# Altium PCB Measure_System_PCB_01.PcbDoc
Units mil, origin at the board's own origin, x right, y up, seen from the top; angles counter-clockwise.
Board outline 2560.03 x 2760.03 mil, 2 copper layers (Top Layer, Bottom Layer); 42 components, 34 nets, 113 pads, 0 vias.
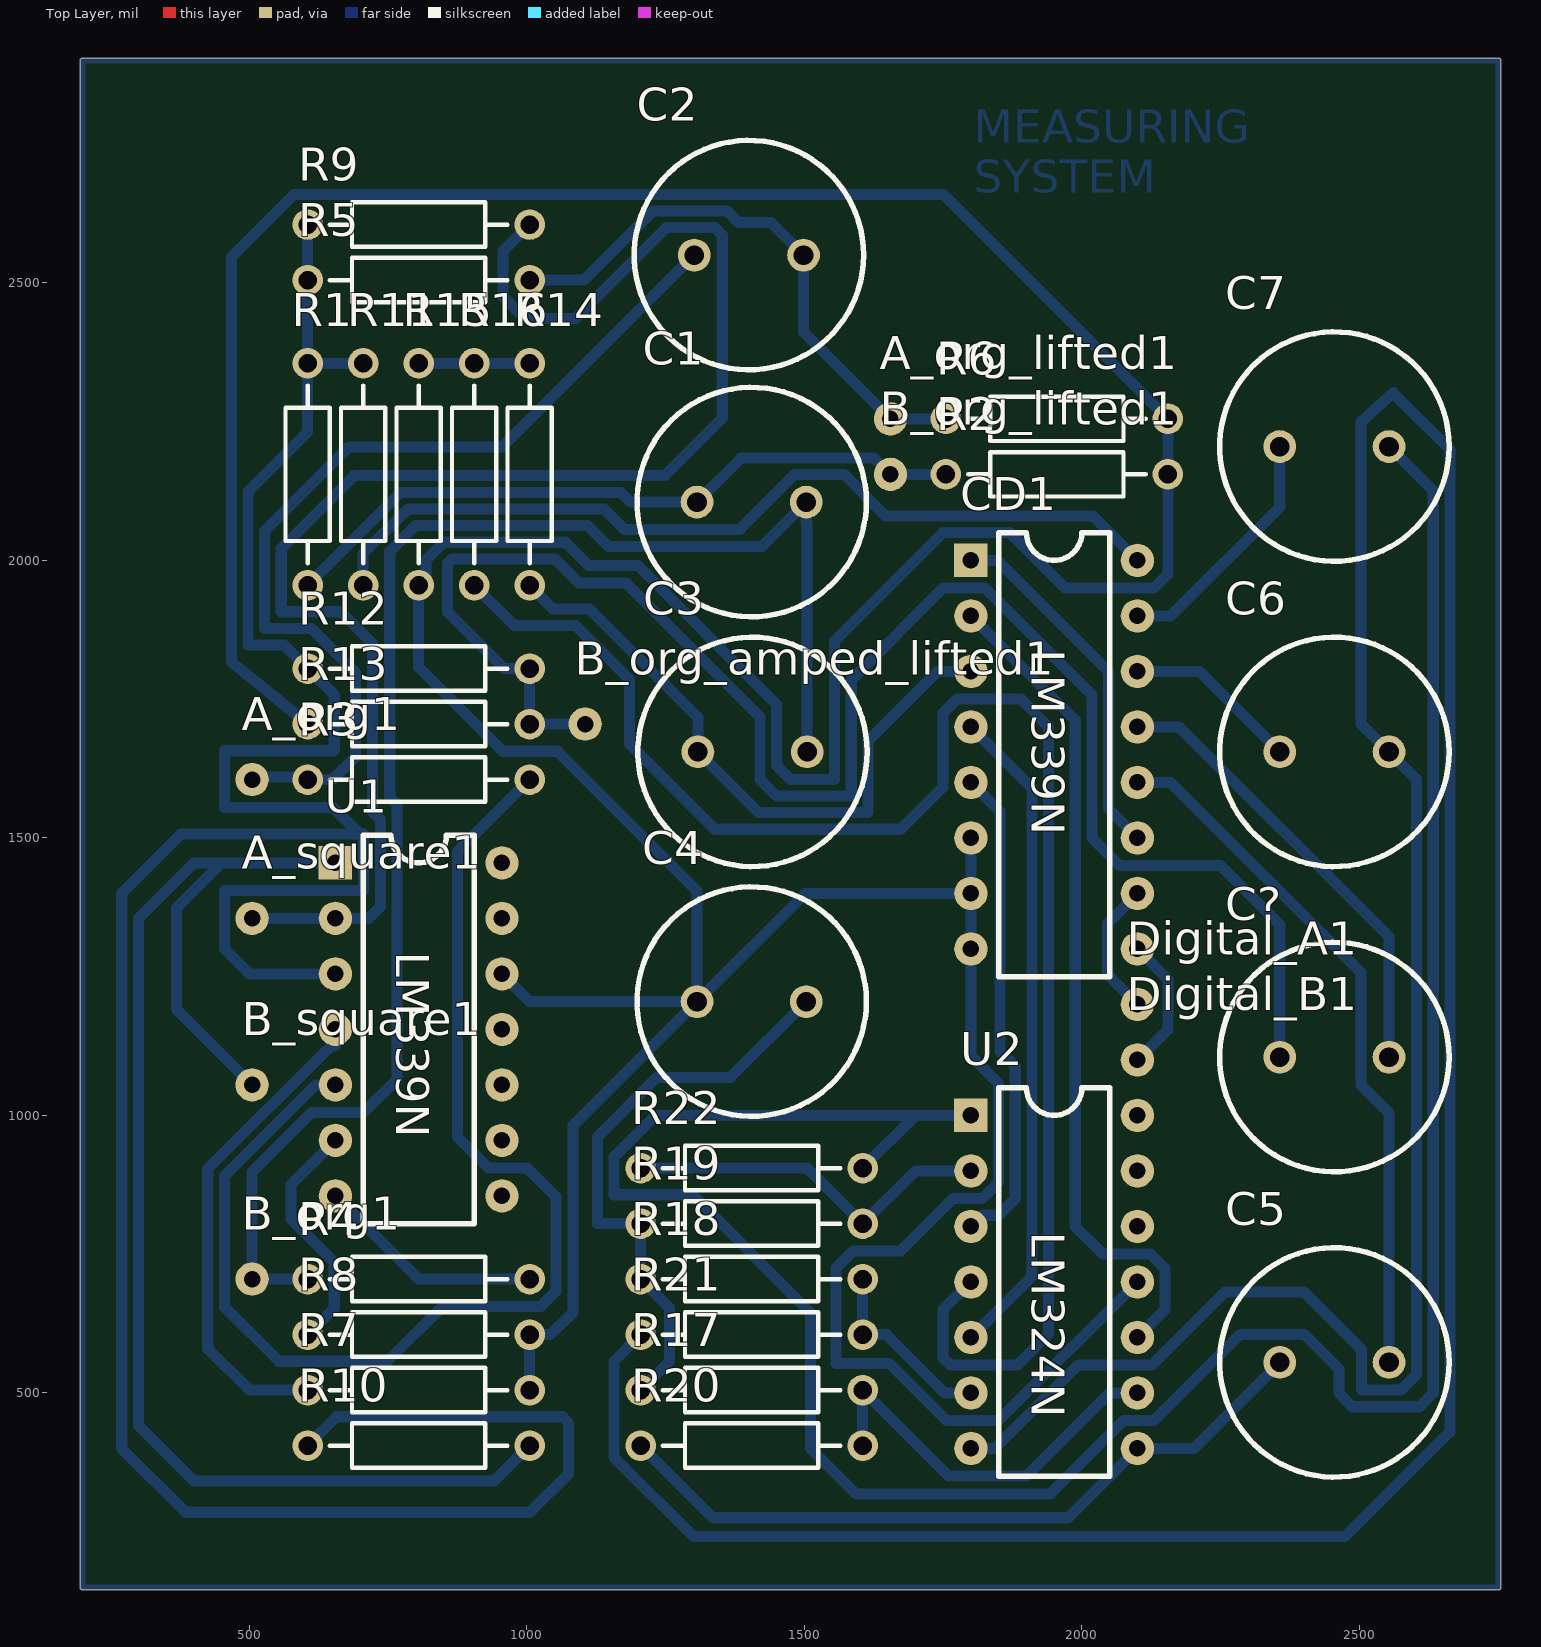
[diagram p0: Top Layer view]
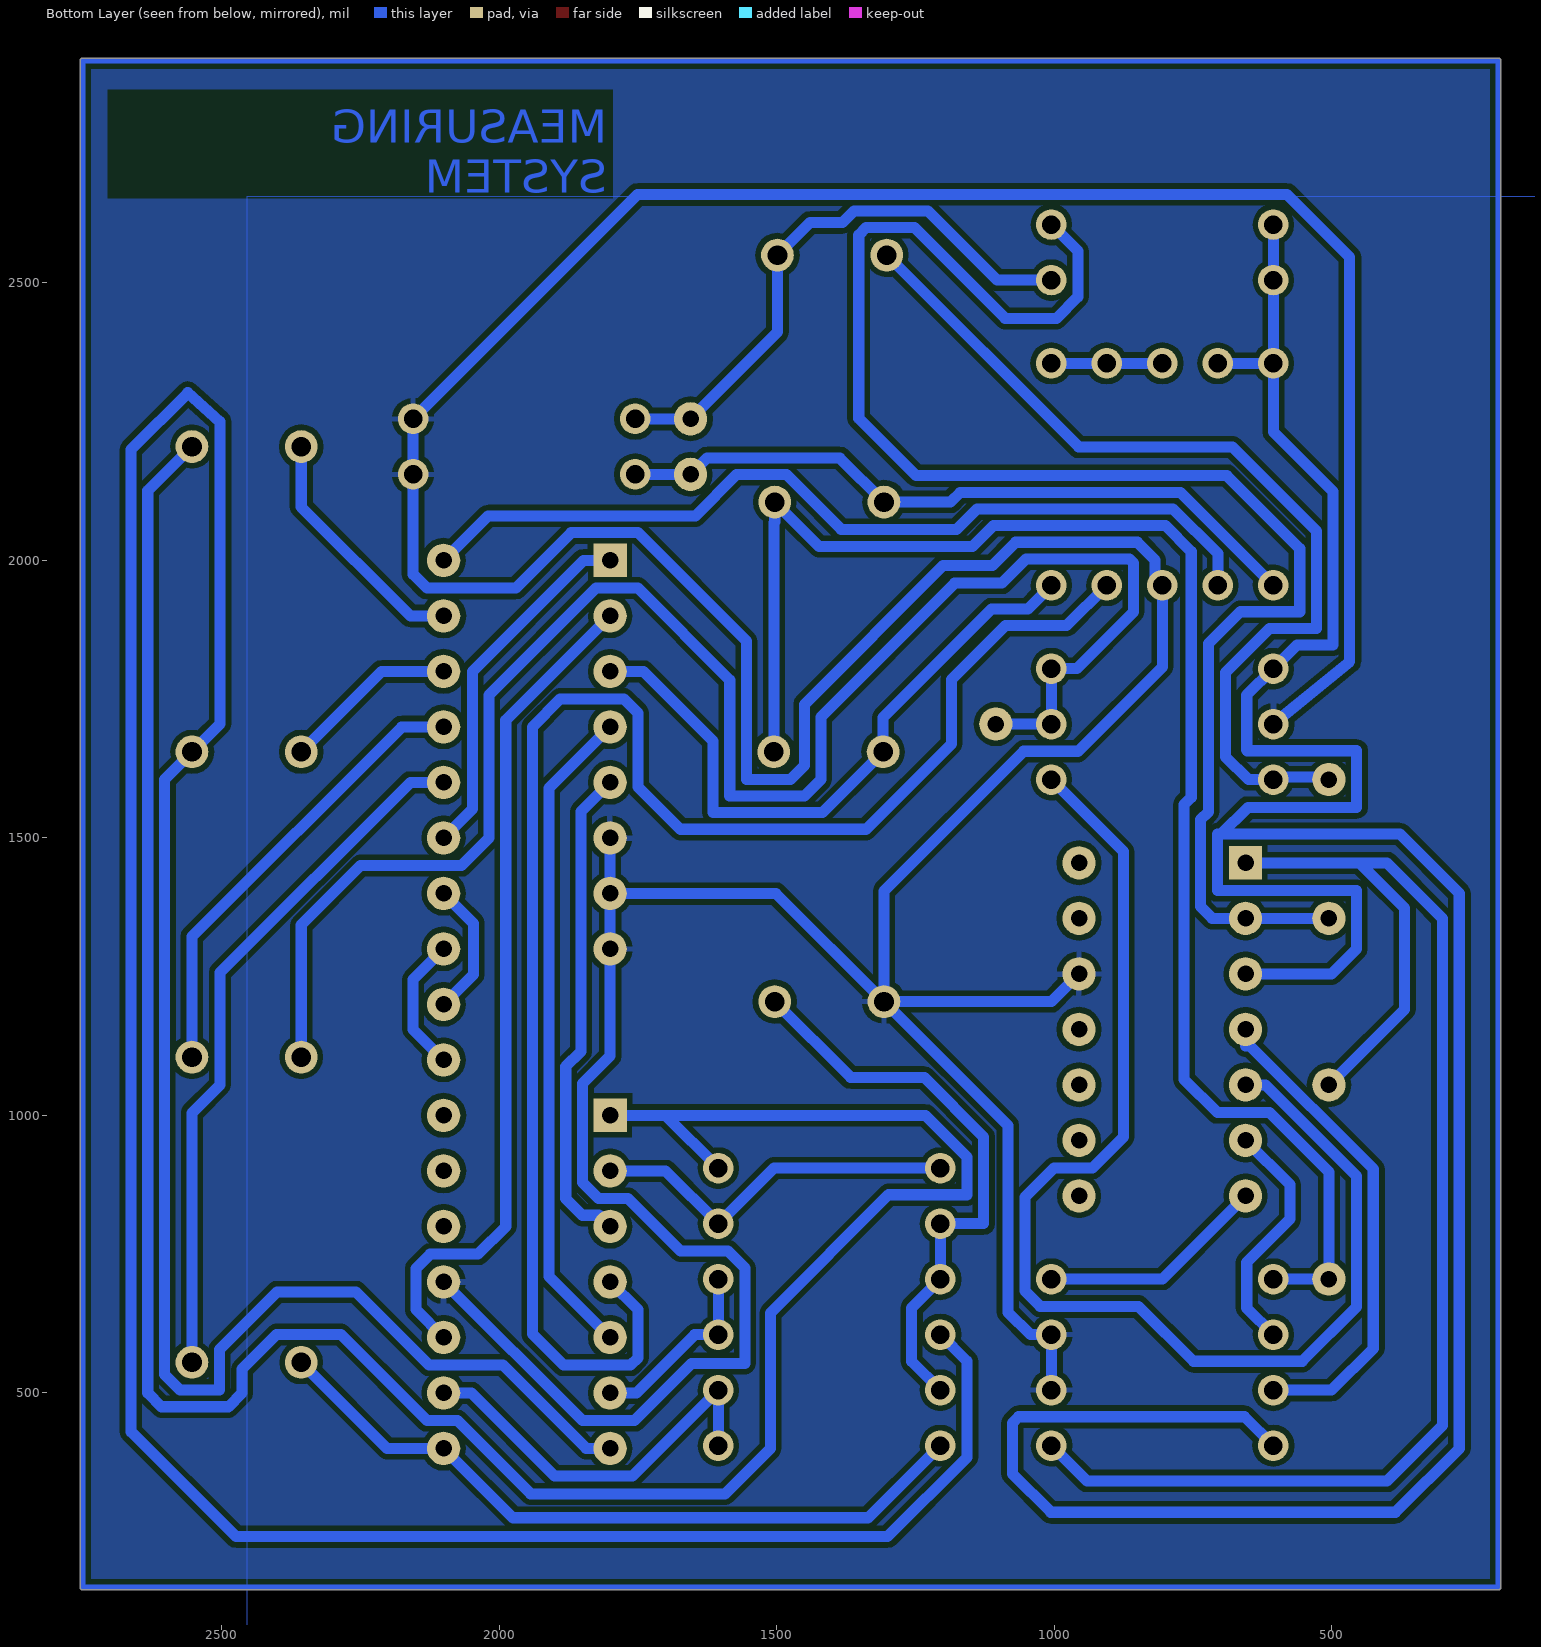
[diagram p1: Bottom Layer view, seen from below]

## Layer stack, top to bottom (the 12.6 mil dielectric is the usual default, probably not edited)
Top Solder: solder mask 0.4, Solder Resist, Dk 3.5
Top Layer: signal copper 1.4
Dielectric 1: dielectric 12.6, FR-4, Dk 4.8
Bottom Layer: signal copper 1.4
Bottom Solder: solder mask 0.4, Solder Resist, Dk 3.5

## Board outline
195.14,151.25 cw(c200,152.51) 194.99,152.51 194.99,2900 cw(c200,2900) 200,2905.01 2750,2905.01 cw(c2750,2900) 2755.01,2900 2755.01,150 cw(c2750,150) 2750,144.99 200,144.99 cw(c200,150)

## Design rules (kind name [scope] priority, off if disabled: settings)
Clearance [All] p1: gap=10 ignorepadtopadclearanceinfootprint=FALSE
PolygonConnect [All] p1: connectstyle=Relief reliefconductorwidth=10 reliefentries=4 polygonreliefangle="90 Angle" airgapwidth=10
RoutingLayers [All] p1: top layer_v5=FALSE bottom layer_v5=TRUE
RoutingVias [All] p1: holewidth=28 width=50 viastyle="Through Hole" minholewidth=28 minwidth=50 maxholewidth=28 maxwidth=50
SolderMaskExpansion [All] p1: expansion=4 istentingtop=FALSE
Width [All] p1: maxlimit=200 minlimit=20 preferedwidth=20 minimp=50.000000 maximp=50.000000 favimp=50.000000
29 further rules are at their usual default settings.

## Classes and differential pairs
component class Part_Square: C1 C2 R1 R2 R3 R4 R5 R6 R7 R8 R9 R10 U1
component class Part_PGA: C3 C4 C5 C6 C7 C? CD1 R11 R12 R13 R14 R15 R16 R17 R18 R19 R20 R21 R22 U2
component class Measure_System_Main: A_org1 A_org_lifted1 A_square1 B_org1 B_org_amped_lifted1 B_org_lifted1 B_square1 Digital_A1 Digital_B1

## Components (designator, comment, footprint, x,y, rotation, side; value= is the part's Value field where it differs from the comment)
A_org1 "Hole" Hole 505.01,1605.02 r270 top
A_org_lifted1 "Hole" Hole 1655.02,2255.01 r90 top
A_square1 "Hole" Hole 505.01,1355.02 r270 top
B_org1 "Hole" Hole 505.01,705.01 r90 top
B_org_amped_lifted1 "Hole" Hole 1105.02,1705.02 r90 top
B_org_lifted1 "Hole" Hole 1655.02,2155.01 r90 top
B_square1 "Hole" Hole 505.01,1055.02 r270 top
C1 "Cap Pol1" RB5-10.5 1405.02,2105.01 r180 top value=10u
C2 "Cap Pol1" RB5-10.5 1400,2550 r0 top value=10u
C3 "Cap Pol1" RB5-10.5 1406.59,1655.02 r180 top value=10u
C4 "Cap Pol1" RB5-10.5 1405.02,1205.02 r0 top value=10u
C5 "Cap Pol1" RB5-10.5 2455.01,555.01 r0 top value=10u
C6 "Cap Pol1" RB5-10.5 2455.01,1655.02 r180 top value=10u
C7 "Cap Pol1" RB5-10.5 2455.01,2205.01 r180 top value=10u
C? "Cap Pol1" RB5-10.5 2455.01,1105.02 r180 top value=10u
CD1 "CD4052" CD4052 1800,2000 r0 top
Digital_A1 "Hole" Hole 2100,1200 r180 top
Digital_B1 "Hole" Hole 2100,1100 r180 top
R1 "Res2" AXIAL-0.4 605.01,2155.01 r90 top value=100k
R2 "Res2" AXIAL-0.4 1955.02,2155.01 r180 top value=100k
R3 "Res2" AXIAL-0.4 805.01,1605.02 r180 top value=1k
R4 "Res2" AXIAL-0.4 805.01,705.01 r180 top value=1k
R5 "Res2" AXIAL-0.4 805.01,2505.01 r180 top value=100k
R6 "Res2" AXIAL-0.4 1955.02,2255.01 r180 top value=100k
R7 "Res2" AXIAL-0.4 805.01,505.01 r180 top value=10k
R8 "Res2" AXIAL-0.4 805.01,605.01 r0 top value=10k
R9 "Res2" AXIAL-0.4 805.01,2605.01 r0 top value=10k
R10 "Res2" AXIAL-0.4 805.01,405.01 r180 top value=10k
R11 "Res2" AXIAL-0.4 705.01,2155.01 r90 top value=200
R12 "Res2" AXIAL-0.4 805.01,1805.02 r180 top value=100k
R13 "Res2" AXIAL-0.4 805.01,1705.02 r0 top value=100k
R14 "Res2" AXIAL-0.4 1005.01,2155.01 r270 top value=100k
R15 "Res2" AXIAL-0.4 805.01,2155.01 r90 top value=100k
R16 "Res2" AXIAL-0.4 905.01,2155.01 r90 top value=100k
R17 "Res2" AXIAL-0.4 1405.02,505.01 r0 top value=50k
R18 "Res2" AXIAL-0.4 1405.02,705.01 r0 top value=24k
R19 "Res2" AXIAL-0.4 1405.02,805.01 r0 top value=12k
R20 "Res2" AXIAL-0.4 1405.02,405.01 r180 top value=100k
R21 "Res2" AXIAL-0.4 1405.02,605.01 r180 top value=100k
R22 "Res2" AXIAL-0.4 1405.02,905.01 r0 top value=100k
U1 "LM339N" LM339N 655.01,1455.02 r0 top
U2 "LM324N" LM324N 1800,1000 r0 top

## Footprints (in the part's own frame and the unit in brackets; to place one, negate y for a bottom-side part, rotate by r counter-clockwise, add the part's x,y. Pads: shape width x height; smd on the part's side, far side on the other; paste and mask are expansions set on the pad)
AXIAL-0.4 [mm] "Axial Device, Thru-Hole; 2 Leads; 0.4 in Pin Spacing"
  round 1.4 hole 0.85: 1(-5.08,0) 2(5.08,0)
  silkscreen extent -4.06,-1.02 4.06,1.02
CD4052 [mil]
  rect 60x60 hole 30: 1(0,0)
  round 60 hole 30 mask+4: 2(0,-100) 3(0,-200) 4(0,-300) 5(0,-400) 6(0,-500) 7(0,-600) 8(0,-700) 9(300,-700) 10(300,-600) 11(300,-500) 12(300,-400) 13(300,-300) 14(300,-200) 15(300,-100) 16(300,0)
  silkscreen extent 50,-750 250,50
Hole [mil]
  round 60 hole 30 mask+4: 1(0,0)
LM324N [mil]
  rect 60x60 hole 30: 1(0,0)
  round 60 hole 30 mask+4: 2(0,-100) 3(0,-200) 4(0,-300) 5(0,-400) 6(0,-500) 7(0,-600) 8(300,-600) 9(300,-500) 10(300,-400) 11(300,-300) 12(300,-200) 13(300,-100) 14(300,0)
  silkscreen extent 50,-650 250,50
LM339N [mil]
  rect 60x60 hole 30: 1(0,0)
  round 60 hole 30 mask+4: 2(0,-100) 3(0,-200) 4(0,-300) 5(0,-400) 6(0,-500) 7(0,-600) 8(300,-600) 9(300,-500) 10(300,-400) 11(300,-300) 12(300,-200) 13(300,-100) 14(300,0)
  silkscreen extent 50,-650 250,50
RB5-10.5 [mm] "Capacitor (Radial); 2 Leads"
  round 1.5 hole 0.9: 1(-2.5,0) 2(2.5,0)
  silkscreen extent -5.25,-5.25 5.25,5.25

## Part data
C1 C2 C3 C4 C5 C6 C7 C?: "Polarized Capacitor (Radial)"
R1 R2 R3 R4 R5 R6 R7 R8 R9 R10 R11 R12 R13 R14 R15 R16 R17 R18 R19 R20 R21 R22: "Resistor"

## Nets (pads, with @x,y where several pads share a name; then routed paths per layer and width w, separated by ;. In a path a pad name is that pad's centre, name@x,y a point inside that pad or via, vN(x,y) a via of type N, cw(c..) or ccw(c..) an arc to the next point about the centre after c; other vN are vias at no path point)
+5: R1.2 R5.2 R9.1 R10.2 R11.2 R12.2 U1.3 | length 5394.6
  Bottom Layer w20: R10.2 657,457 1064,457 1075,446 1075,354 1006,285 385,285 270,400 270,1400 377,1507 699,1507 ; R9.1 R5.2 R1.2 ; U1.3 499.98,1255.02 455,1300 455,1405.02 706,1405.02 706,1500 ; R11.2 R1.2 ; R1.2 605.02,2231.7 497.46,2124.14 497.46,1847.46 562.58,1847.46 R12.2 653,1757.03 653,1658 652,1657 455,1657 455,1555 651,1555 699,1507 ; 699,1507 706,1500 ; 699,1507 706,1507 706,1500
+12: R16.1 U2.4 | length 2950.8
  Bottom Layer w20: R16.1 977.46,1882.58 1087.44,1882.58 1185.02,1785 1185.02,1669.49 1339.02,1515.49 1673.49,1515.49 1750,1592 1750,1725 1775,1750 1890,1750 1940,1700 1940,606 1884,550 1763,550 1750,563 1750,650 U2.4
B_org: B_org1.1 C1.1 C3.1 R4.2 | length 2848.7
  Bottom Layer w20: R4.2 B_org1.1 505.02,898.16 611.87,1005.02 706,1005.02 766,1065.02 766,1560 753,1573 753,2016 799.58,2062.58 1109.15,2062.58 1146.72,2025 1423.43,2025 C1.1 1503.44,2069.44 1505.02,2067.87 C3.1
B_org_amp_1: CD1.1 CD1.11 | length 652.4
  Bottom Layer w20: CD1.1 1848,2000 2048,1800 2048,1552 CD1.11
B_org_amp_2.5: C5.2 CD1.12 | length 1268
  Bottom Layer w20: CD1.12 2160,1600 2503,1257 2503,1055 2553.44,1004.56 C5.2
B_org_amp_5: C6.2 CD1.14 | length 316.6
  Bottom Layer w20: CD1.14 2211.61,1800 C6.2
B_org_amp_10: C7.2 CD1.15 | length 446.4
  Bottom Layer w20: CD1.15 2160,1900 2356.59,2096.59 C7.2
B_org_amped: C?.1 CD1.13 | length 826.9
  Bottom Layer w20: CD1.13 2175.35,1700 2553.44,1321.91 C?.1
B_org_to_amp: C3.2 CD1.3 R14.2 | length 1181.9
  Bottom Layer w20: R14.2 1047.46,1912.58 1112.58,1912.58 1308.16,1716.99 C3.2 1417.69,1545.49 1614.54,1545.49 1614.54,1674.54 1740,1800 CD1.3
B_org_to_amp_2.5: CD1.2 U2.10 | length 1516.1
  Bottom Layer w20: CD1.2 1988,1712 1988,800 2038,750 2124,750 2150,724 2150,650 U2.10
B_org_to_amp_5: CD1.4 U2.5 | length 1191.1
  Bottom Layer w20: U2.5 1910,710 1910,1590 CD1.4
B_org_to_amp_10: CD1.5 U2.3 | length 883.8
  Bottom Layer w20: U2.3 1820,820 1850,820 1880,850 1880,1087.67 1852.18,1115.49 1852.18,1547.82 CD1.5
Digital_A: CD1.10 Digital_A1.1 | length 244.7
  Bottom Layer w20: Digital_A1.1 2046,1254 2046,1346 CD1.10
Digital_B: CD1.9 Digital_B1.1 | length 245.6
  Bottom Layer w20: Digital_B1.1 2155,1155 2155,1245 CD1.9
GND: C4.1 CD1.6 CD1.7 CD1.8 R2.1 R6.1 R7.1 R8.2 R13.1 R15.1 U1.12 U2.11 | length 9781.4
  Bottom Layer w20: R13.1 467.46,1817.46 467.46,2546.46 580.53,2659.53 1750.5,2659.53 R6.1 R2.1 2155.02,1975 2130.02,1950 1970,1950 1870,2050 1750,2050 1554.54,1854.54 1554.54,1605.49 1475,1605.49 1450,1630.49 1450,1740.63 1200,1990.63 1111.37,1990.63 1069.42,2032.58 850,2032.58 818.29,2000.87 818.29,1968.29 R15.1 805.02,1807.98 957,1656 1055,1656 1306.59,1404.41 C4.1 ; U1.12 1005.02,1205.02 C4.1 ; R7.1 R8.2 1042.92,605.02 1083,645.1 1083,981.43 C4.1 ; CD1.6 CD1.7 ; U2.11 1850,450 1756,450 1653,553 1557,553 1557,725 1588,756 1673.48,756 1767.48,850 1820.71,850 1850,879.29 1850,1057 1800,1107 CD1.8 CD1.7 ; C4.1 1501.57,1400 CD1.7
NetA_org1_1: A_org1.1 C2.1 R3.2 | length 1713.4
  Bottom Layer w20: A_org1.1 505.02,1609.51 600.52,1609.51 R3.2 650,1605.02 691.02,1646.03 691.02,1798.11 611.67,1877.46 527.46,1877.46 527.46,2053.11 678.34,2204 955.57,2204 C2.1
NetA_org_lifted1_1: A_org_lifted1.1 C2.2 R5.1 R6.2 | length 1037.8
  Bottom Layer w20: R5.1 1103.02,2505.02 1227.53,2629.53 1360.49,2629.53 1381.1,2608.92 1439.51,2608.92 C2.2 1498.43,2411.61 A_org_lifted1.1 R6.2
NetA_square1_1: A_square1.1 R9.2 U1.2 | length 2878.2
  Bottom Layer w20: A_square1.1 U1.2 715.02,1355.02 736,1376 736,1533 722,1547 722,1850 664.54,1907.46 557.46,1907.46 557.46,2021.46 689,2153 1249,2153 1352,2256 1352,2586.53 1339,2599.53 1251.53,2599.53 1088,2436 996,2436 957,2475 957,2557 R9.2
NetB_org_amped_lifted1_1: B_org_amped_lifted1.1 C?.2 R12.1 R13.2 | length 3141.7
  Bottom Layer w20: B_org_amped_lifted1.1 R13.2 R12.1 958.98,1805.02 857,1907 857,1995.58 864,2002.58 1050.42,2002.58 1094,1959 1179,1959 1420,1718 1420,1605.49 1450,1575.49 1584.54,1575.49 1584.54,1784.54 1750,1950 1825,1950 2018,1757 2018,1500 2068,1450 2249.59,1450 2356.59,1343 C?.2
NetB_org_lifted1_1: B_org_lifted1.1 C1.2 R1.1 R2.2 | length 1272
  Bottom Layer w20: R1.1 772.58,2122.58 1169.15,2122.58 1186.71,2105.02 C1.2 1386.27,2184.69 1625.34,2184.69 B_org_lifted1.1 R2.2
NetB_square1_1: B_square1.1 R10.1 U1.1 | length 2573.3
  Bottom Layer w20: B_square1.1 368.98,1191.05 368.98,1374 450,1455.02 ; U1.1 450,1455.02 ; R10.1 941,341 400,341 300,441 300,1355.02 400,1455.02 450,1455.02
NetC4_2: C4.2 R17.1 R18.1 R19.1 | length 1054.6
  Bottom Layer w20: R17.1 1257,557 1257,653.03 R18.1 R19.1 1127,805.02 1127,961 1234,1068 1366.43,1068 C4.2
NetC5_1: C5.1 R20.2 U2.8 | length 1321.4
  Bottom Layer w20: R20.2 1335.03,275 1975,275 U2.8 2201.57,400 C5.1
NetC6_1: C6.1 R21.2 U2.7 | length 6681.5
  Bottom Layer w20: R21.2 1157,557 1157,384 1300,241 2474,241 2663,430 2663,2200 2561,2302 2503,2250 2503,1705.46 C6.1 2602.97,1605.49 2602.97,533.46 2575,505.49 2503.91,505.49 2503.91,578.09 2400,682 2258,682 2126,550 1993,550 1843,400 U2.7
NetC7_1: C7.1 R22.2 U2.1 | length 4664.8
  Bottom Layer w20: R22.2 1700,1000 ; U2.1 1700,1000 ; C7.1 2633,2125.46 2633,500 2608,475 2488,475 2463,500 2463,543 2401,605 2285,605 2130,450 2075,450 1943,318 1593,318 1511,400 1511,644 1298,857 1157,857 1157,925 1232,1000 1700,1000
NetCD1_16: CD1.16 R11.1 | length 1605.8
  Bottom Layer w20: R11.1 705.02,2012 785.59,2092.58 1139.15,2092.58 1176.24,2055.49 1383.49,2055.49 1482.54,2154.54 1572,2154.54 1646.54,2080 2020,2080 CD1.16
NetR3_1: R3.1 U1.5 | length 2283.9
  Bottom Layer w20: U1.5 619.44,1055.02 455,890.57 455,655 553,557 749,557 848,656 1025,656 1052.58,683.58 1052.58,853 1000.56,905.02 931.03,905.02 875.02,961.03 875.02,1475.02 R3.1
NetR4_1: R4.1 U1.7 | length 412.1
  Bottom Layer w20: U1.7 805.02,705.02 R4.1
NetR7_2: R7.2 U1.4 | length 886.1
  Bottom Layer w20: R7.2 500,505.02 425,580.02 425,903 647,1125 655.02,1125 U1.4
NetR8_1: R8.1 U1.6 | length 435.3
  Bottom Layer w20: R8.1 653,653 653,734.98 575.02,812.96 575.02,875.02 U1.6
NetR14_1: R14.1 R15.2 R16.2 | length 200
  Bottom Layer w20: R15.2 R16.2 R14.1
NetR17_2: R17.2 R20.1 U2.9 | length 721.3
  Bottom Layer w20: R20.1 R17.2 1760.03,350 1900.18,350 2050.18,500 U2.9
NetR18_2: R18.2 R21.1 U2.6 | length 338.5
  Bottom Layer w20: R18.2 R21.1 1647.48,605.02 1752.5,500 U2.6
NetR19_2: R19.2 R22.1 U2.2 | length 675.7
  Bottom Layer w20: R22.1 1505.02,905.02 R19.2 1700,900 U2.2
pads on no net: U1.8 U1.9 U1.10 U1.11 U1.13 U1.14 U2.12 U2.13 U2.14
copper on no net: | length 10597.5
  Bottom Layer w10: 200,150 2750,150 2750,2900 200,2900 200,152.51

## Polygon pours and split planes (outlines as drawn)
GND on Bottom Layer "NONET_L-01_P-001" (solid, pour order 4): 200,2900 2750,2900 2750,150 205.02,155.02 200,150
no net on Bottom Layer "NONET_L-01_P-001" (solid, remove dead copper, shelved, pour order 3): 5.01,2655.01 2455.01,2655.01 2455.01,5.01 5.01,5.01

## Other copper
Bottom Layer:
  text "MEASURING / SYSTEM" at 1805.14,2662.02 h60

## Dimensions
200,2900 to 2750,2900 on Bottom Layer
2750,2900 to 2750,150 on Bottom Layer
